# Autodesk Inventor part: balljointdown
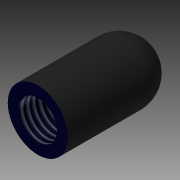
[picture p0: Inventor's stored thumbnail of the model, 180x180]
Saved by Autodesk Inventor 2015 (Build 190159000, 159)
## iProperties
Created: 2015-02
Part Number: balljointdown
Material: ABS Plastic
Document SubType Name: Modeling
Designer: sungeun
Density: 1.06 g/cm^3
Appearance: Smooth - White
Author: sungeun
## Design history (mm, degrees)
sketch "Sketch1"
  geometry: L1 (0, 0)-(-10, 0); L2 (-10, 0)-(-10, 21.905); L3 (-10, 27.425)-(-10, 21.905); L4 (0, 20)-(0, 0); L5 (0, 27)-(0.772, 22.622); L6 (-6.428, 34.66)-(-5.775, 30.956); A1 r 7 centre (0, 27) between (-5.775, 30.956) and (0, 20); A2 r 10 centre (0, 27) between (-6.428, 34.66) and (-10, 27)
  constraints: 12 end point, 4 point on circle, 2 centre point, 2 point on line, 2 vertical, 1 coincident, 1 horizontal, 1 parallel, 1 perpendicular, 1 tangent, 1 vertical alignment
  dimensions: "d2" = 10 distance of L1.start L1.end; "d3" = 20 distance of L4.start L1.start; "d5" = 170 deg angle of L4 L5; "d6" = 5 distance between parallel lines of L5 L6; "d7" = 7 radius of A1
revolve "Revolution1" sketch "Sketch1" stored, may be unused: angle "d8" = 90 deg
sketch "Sketch2"
  geometry: C1 r 6.35 at (0, 0); 1 further point
  constraints: 1 centre point, 1 coincident
  dimensions: "d9" = 12.7 diameter of C1
extrude "Extrusion1" cut sketch "Sketch2" distance "d10" = 15; taper "d11" = 0 deg
thread "Thread1" dims "d12" = 10, "d13" = 0
body "Solid1"
